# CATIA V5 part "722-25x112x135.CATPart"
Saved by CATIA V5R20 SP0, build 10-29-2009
Part number: 722-25x112x135
Definition: NONE
Nomenclature: 722-25x112x135
Source: Unknown
Description: 722-25x112x135
Bounding box of the stored display mesh (mm): x -12.5 to 12.5, y -12.5 to 12.5, z -100 to 35
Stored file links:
  C:\Users\Utente\Desktop\IO LAVORO\3D X SITO CF\X SITO\722\722-25x112x135.CATPart
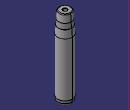
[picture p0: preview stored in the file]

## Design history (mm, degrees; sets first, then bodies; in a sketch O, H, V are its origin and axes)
Body1 "722-25x112x135" (main body)
  Solid1: solid without history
